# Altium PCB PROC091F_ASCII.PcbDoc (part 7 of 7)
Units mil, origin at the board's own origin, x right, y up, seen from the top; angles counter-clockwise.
Board outline 3590.95 x 906.17 mil, 8 copper layers (Top Layer, GND1, Sig1, PWR1, PWR2, Sig2, GND2, Bottom Layer), stack 63.146 mil thick; 420 components, 316 nets, 1432 pads, 774 vias.
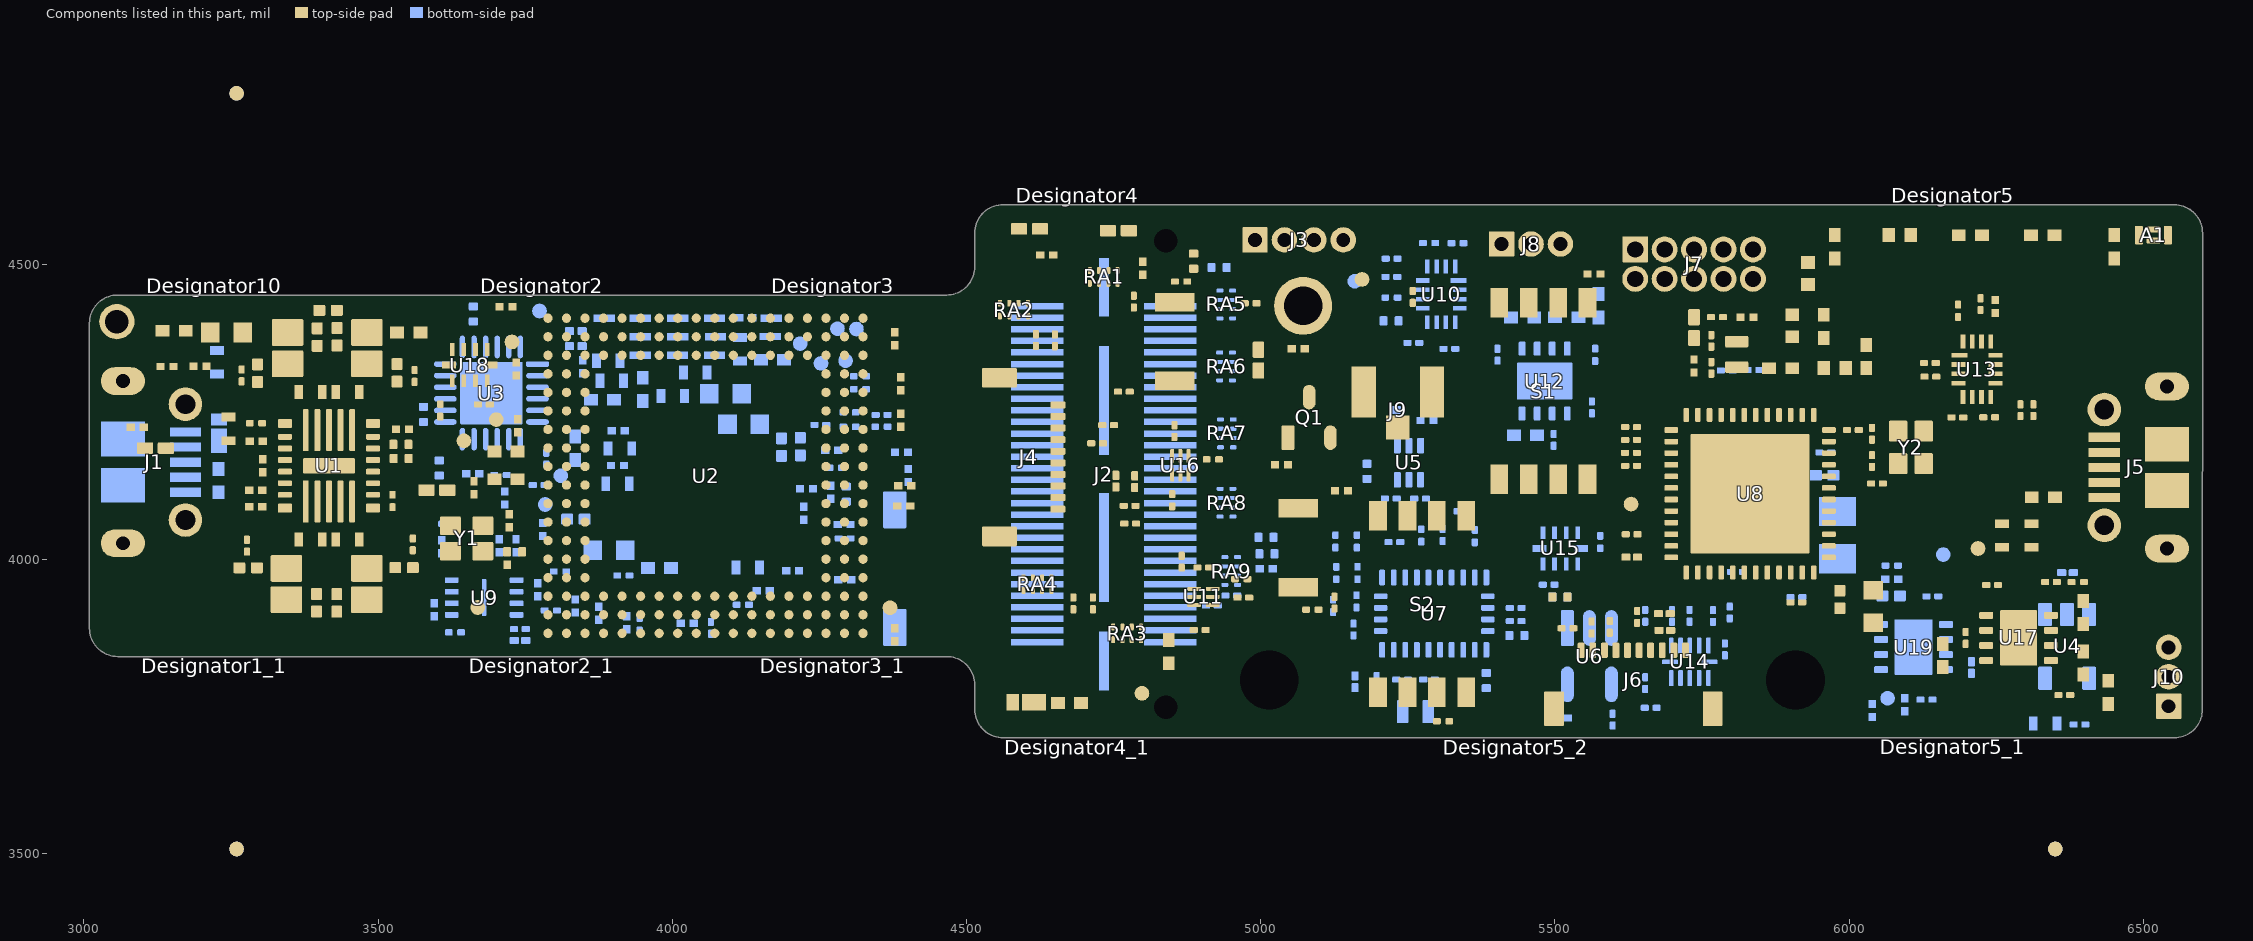
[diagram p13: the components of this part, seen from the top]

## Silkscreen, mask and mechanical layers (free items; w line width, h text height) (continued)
M12 Stackup:
  drawing of 503 lines, arcs and shapes, not listed
  text "Layer" at 8.08,2102.3 h60
  text "Name" at 417.99,2102.3 h60
  text "Material" at 1347.73,2102.3 h60
  text "Thickness" at 2207.5,2102.3 h60
  text "Constant" at 2857.34,2102.3 h60
  text "Board Layer Stack" at 3427.2,2102.3 h60
  text "1" at 8.08,1982.3 h60
  text "Top Overlay" at 417.99,1982.3 h60
  text "2" at 8.08,1862.3 h60
  text "Top Solder" at 417.99,1862.3 h60
  text "Solder Resist" at 1347.73,1862.3 h60
  text "0.50mil" at 2207.5,1862.3 h60
  text "3.5" at 2857.34,1862.3 h60
  text "3" at 8.08,1742.3 h60
  text "Top Layer" at 417.99,1742.3 h60
  text "Copper" at 1347.73,1742.3 h60
  text "1.37mil" at 2207.5,1742.3 h60
  text "4" at 8.08,1622.3 h60
  text "Dielectric1" at 417.99,1622.3 h60
  text "FR-4 High Tg" at 1347.73,1622.3 h60
  text "3.70mil" at 2207.5,1622.3 h60
  text "4.2" at 2857.34,1622.3 h60
  text "5" at 8.08,1502.3 h60
  text "GND1" at 417.99,1502.3 h60
  text "Copper" at 1347.73,1502.3 h60
  text "2.40mil" at 2207.5,1502.3 h60
  text "6" at 8.08,1382.3 h60
  text "Dielectric3" at 417.99,1382.3 h60
  text "FR-4 High Tg" at 1347.73,1382.3 h60
  text "4.50mil" at 2207.5,1382.3 h60
  text "4.2" at 2857.34,1382.3 h60
  text "7" at 8.08,1262.3 h60
  text "Sig1" at 417.99,1262.3 h60
  text "Copper" at 1347.73,1262.3 h60
  text "1.20mil" at 2207.5,1262.3 h60
  text "8" at 8.08,1142.3 h60
  text "Dielectric2" at 417.99,1142.3 h60
  text "FR-4 High Tg" at 1347.73,1142.3 h60
  text "12.00mil" at 2207.5,1142.3 h60
  text "4.2" at 2857.34,1142.3 h60
  text "9" at 8.08,1022.3 h60
  text "PWR1" at 417.99,1022.3 h60
  text "Copper" at 1347.73,1022.3 h60
  text "2.40mil" at 2207.5,1022.3 h60
  text "10" at 8.08,902.3 h60
  text "Dielectric4" at 417.99,902.3 h60
  text "FR-4 High Tg" at 1347.73,902.3 h60
  text "8.00mil" at 2207.5,902.3 h60
  text "4.2" at 2857.34,902.3 h60
  text "11" at 8.08,782.3 h60
  text "PWR2" at 417.99,782.3 h60
  text "Copper" at 1347.73,782.3 h60
  text "2.40mil" at 2207.5,782.3 h60
  text "12" at 8.08,662.3 h60
  text "Dielectric5" at 417.99,662.3 h60
  text "FR-4 High Tg" at 1347.73,662.3 h60
  text "12.00mil" at 2207.5,662.3 h60
  text "4.2" at 2857.34,662.3 h60
  text "13" at 8.08,542.3 h60
  text "Sig2" at 417.99,542.3 h60
  text "Copper" at 1347.73,542.3 h60
  text "1.20mil" at 2207.5,542.3 h60
  text "14" at 8.08,422.3 h60
  text "Dielectric8" at 417.99,422.3 h60
  text "FR-4 High Tg" at 1347.73,422.3 h60
  text "4.50mil" at 2207.5,422.3 h60
  text "4.2" at 2857.34,422.3 h60
  text "15" at 8.08,302.3 h60
  text "GND2" at 417.99,302.3 h60
  text "Copper" at 1347.73,302.3 h60
  text "2.40mil" at 2207.5,302.3 h60
  text "16" at 8.08,182.3 h60
  text "Dielectric9" at 417.99,182.3 h60
  text "FR-4 High Tg" at 1347.73,182.3 h60
  text "3.70mil" at 2207.5,182.3 h60
  text "4.2" at 2857.34,182.3 h60
  text "17" at 8.08,62.3 h60
  text "Bottom Layer" at 417.99,62.3 h60
  text "Copper" at 1347.73,62.3 h60
  text "1.37mil" at 2207.5,62.3 h60
  text "18" at 8.08,-57.7 h60
  text "Bottom Solder" at 417.99,-57.7 h60
  text "Solder Resist" at 1347.73,-57.7 h60
  text "0.50mil" at 2207.5,-57.7 h60
  text "3.5" at 2857.34,-57.7 h60
  text "19" at 8.08,-177.7 h60
  text "Bottom Overlay" at 417.99,-177.7 h60
  text ".Layer_Name" at 577,-858.49 h60
M13 Component Bodies Top:
  text ".Layer_Name" at 577,-858.49 h60
M14 Component Bodies Bottom:
  text ".Layer_Name" at 577,-858.49 h60
M15 Courtyards Top:
  text ".Layer_Name" at 577,-858.49 h60
M16 Courtyards Bottom:
  text ".Layer_Name" at 577,-858.49 h60
Drill Drawing:
  circle w10: c7603.25,4734.77 r16.58
  circle w10: c7603.25,4734.77 r27.63
  circle w10: c7603.25,3367.25 r27.63
  lines w10: 7575.63,3463.95 7603.25,3477.76 7630.88,3463.95 7617.07,3491.57 7630.88,3519.2 7603.25,3505.39 7575.63,3519.2 7589.44,3491.57 7575.63,3463.95 ; 7575.63,3602.08 7589.44,3602.08 7603.25,3588.27 7617.07,3602.08 7630.88,3602.08 7617.07,3615.89 7630.88,3629.71 7617.07,3629.71 7603.25,3643.52 7589.44,3629.71 7575.63,3629.71 7589.44,3615.89 7575.63,3602.08 ; 7575.63,3726.4 7589.44,3726.4 7589.44,3712.59 7617.07,3712.59 7617.07,3726.4 7630.88,3726.4 7630.88,3754.03 7617.07,3754.03 7617.07,3767.84 7589.44,3767.84 7589.44,3754.03 7575.63,3754.03 7575.63,3726.4 ; 7575.63,3836.91 7603.25,3850.72 7630.88,3836.91 7617.07,3864.53 7630.88,3892.16 7603.25,3878.35 7575.63,3892.16 7589.44,3864.53 7575.63,3836.91 ; 7575.63,3988.85 7603.25,3961.23 7630.88,3988.85 7603.25,4016.48 7575.63,3988.85 ; 7575.63,4099.36 7589.44,4099.36 7589.44,4085.55 7617.07,4085.55 7617.07,4099.36 7630.88,4099.36 7630.88,4126.99 7617.07,4126.99 7617.07,4140.8 7589.44,4140.8 7589.44,4126.99 7575.63,4126.99 7575.63,4099.36 ; 7575.63,4265.12 7630.88,4265.12 7603.25,4209.87 7575.63,4265.12 ; 7575.63,4334.19 7575.63,4348 7589.44,4361.81 7575.63,4375.63 7575.63,4389.44 7589.44,4389.44 7603.25,4375.63 7617.07,4389.44 7630.88,4389.44 7630.88,4375.63 7617.07,4361.81 7630.88,4348 7630.88,4334.19 7617.07,4334.19 7603.25,4348 7589.44,4334.19 7575.63,4334.19 ; 7575.63,4458.51 7630.88,4458.51 7630.88,4513.76 7575.63,4513.76 7575.63,4458.51 ; 7575.63,4638.08 7630.88,4638.08 7603.25,4582.83 7575.63,4638.08 ; 7575.63,4831.47 7630.88,4831.47 7630.88,4886.72 7575.63,4886.72 7575.63,4831.47 ; 7586.68,3475 7603.25,3483.28 7619.83,3475 7611.54,3491.57 7619.83,3508.15 7603.25,3499.86 7586.68,3508.15 7594.97,3491.57 7586.68,3475 ; 7586.68,4104.88 7594.97,4104.88 7594.97,4096.6 7611.54,4096.6 7611.54,4104.88 7619.83,4104.88 7619.83,4121.46 7611.54,4121.46 7611.54,4129.75 7594.97,4129.75 7594.97,4121.46 7586.68,4121.46 7586.68,4104.88 ; 7586.68,4627.03 7619.83,4627.03 7603.25,4593.88 7586.68,4627.03 ; 7586.68,4842.52 7619.83,4842.52 7619.83,4875.67 7586.68,4875.67 7586.68,4842.52
  lines w12: 7525.54,3302.33 10757.03,3302.33 ; 7525.54,4918.49 10757.03,4918.49 ; 7863.4,3178.01 7863.4,5042.81 ; 8195.4,3178.01 8195.4,5042.81 ; 8831.96,3178.01 8831.96,5042.81 ; 9091.1,3178.01 9091.1,5042.81 ; 9466.26,3178.01 9466.26,5042.81 ; 10190.59,3178.01 10190.59,5042.81 ; 7525.54,3178.01 10757.03,3178.01 10757.03,5042.81 7525.54,5042.81 7525.54,3178.01
  text "Symbol" at 7600.13,4955.79 h72
  text "Quantity" at 7900.7,4955.79 h72
  text "Finished Hole Size" at 8232.7,4955.79 h72
  text "Plated" at 8869.26,4955.79 h72
  text "Hole Type" at 9128.4,4955.79 h72
  text "Drill Layer Pair" at 9503.56,4955.79 h72
  text "Hole Tolerance" at 10227.89,4955.79 h72
  text "36" at 7900.7,4831.47 h60
  text "7.87mil" at 8232.7,4831.47 h60
  text "PTH" at 8869.26,4831.47 h60
  text "Round" at 9128.4,4831.47 h60
  text "Top Layer - Bottom Layer" at 9503.56,4831.47 h60
  text "626" at 7900.7,4707.15 h60
  text "8.00mil" at 8232.7,4707.15 h60
  text "PTH" at 8869.26,4707.15 h60
  text "Round" at 9128.4,4707.15 h60
  text "Top Layer - Bottom Layer" at 9503.56,4707.15 h60
  text "112" at 7900.7,4582.83 h60
  text "8.00mil" at 8232.7,4582.83 h60
  text "PTH" at 8869.26,4582.83 h60
  text "Round" at 9128.4,4582.83 h60
  text "Top Layer - Bottom Layer" at 9503.56,4582.83 h60
  text "+/-3.00mil" at 10227.89,4582.83 h60
  text "10" at 7900.7,4458.51 h60
  text "23.62mil" at 8232.7,4458.51 h60
  text "PTH" at 8869.26,4458.51 h60
  text "Round" at 9128.4,4458.51 h60
  text "Top Layer - Bottom Layer" at 9503.56,4458.51 h60
  text "4" at 7900.7,4334.19 h60
  text "23.62mil" at 8232.7,4334.19 h60
  text "PTH" at 8869.26,4334.19 h60
  text "Slot" at 9128.4,4334.19 h60
  text "Top Layer - Bottom Layer" at 9503.56,4334.19 h60
  text "10" at 7900.7,4209.87 h60
  text "27.56mil" at 8232.7,4209.87 h60
  text "PTH" at 8869.26,4209.87 h60
  text "Round" at 9128.4,4209.87 h60
  text "Top Layer - Bottom Layer" at 9503.56,4209.87 h60
  text "33" at 7900.7,4085.55 h60
  text "32.00mil" at 8232.7,4085.55 h60
  text "NPTH" at 8869.26,4085.55 h60
  text "Round" at 9128.4,4085.55 h60
  text "Top Layer - Bottom Layer" at 9503.56,4085.55 h60
  text "4" at 7900.7,3961.23 h60
  text "33.47mil" at 8232.7,3961.23 h60
  text "PTH" at 8869.26,3961.23 h60
  text "Round" at 9128.4,3961.23 h60
  text "Top Layer - Bottom Layer" at 9503.56,3961.23 h60
  text "1" at 7900.7,3836.91 h60
  text "40.00mil" at 8232.7,3836.91 h60
  text "PTH" at 8869.26,3836.91 h60
  text "Round" at 9128.4,3836.91 h60
  text "Top Layer - Bottom Layer" at 9503.56,3836.91 h60
  text "2" at 7900.7,3712.59 h60
  text "40.16mil" at 8232.7,3712.59 h60
  text "NPTH" at 8869.26,3712.59 h60
  text "Round" at 9128.4,3712.59 h60
  text "Top Layer - Bottom Layer" at 9503.56,3712.59 h60
  text "1" at 7900.7,3588.27 h60
  text "64.96mil" at 8232.7,3588.27 h60
  text "PTH" at 8869.26,3588.27 h60
  text "Round" at 9128.4,3588.27 h60
  text "Top Layer - Bottom Layer" at 9503.56,3588.27 h60
  text "4" at 7900.7,3463.95 h60
  text "88.00mil" at 8232.7,3463.95 h60
  text "NPTH" at 8869.26,3463.95 h60
  text "Round" at 9128.4,3463.95 h60
  text "Top Layer - Bottom Layer" at 9503.56,3463.95 h60
  text "+/-3.00mil" at 10227.89,3463.95 h60
  text "2" at 7900.7,3339.63 h60
  text "100.00mil" at 8232.7,3339.63 h60
  text "NPTH" at 8869.26,3339.63 h60
  text "Round" at 9128.4,3339.63 h60
  text "Top Layer - Bottom Layer" at 9503.56,3339.63 h60
  text "+/-3.00mil" at 10227.89,3339.63 h60
  text "845 Total" at 7900.7,3215.31 h60
  text "Slot definitions :" at 7600.13,3128.28 h60
  text "Routed Path Length" at 8050.85,3128.28 h60
  text "= Calculated from tool start centre position to tool end centre position." at 8590.58,3128.28 h60
  text "Hole Length" at 8050.85,3078.55 h60
  text "= Routed Path Length + Tool Size = Slot length as defined in the PCB layout" at 8390.78,3078.55 h60
  text ".Layer_Name" at 577,-858.49 h60
M17 Embedded Cavity:
  text ".Layer_Name" at 577,-858.49 h60
M18 Embedded Assembly:
  text ".Layer_Name" at 577,-858.49 h60
M19 Embedded Keepout:
  text ".Layer_Name" at 577,-858.49 h60
Mechanical 21:
  text "Works With TI LaunchPad Logo1" at 56021.02,58034.06 h60
  text "Works With TI LaunchPad Logo1" at 56021.02,58034.06 h60
  text "Logo2" at 54657.52,57702.56 h60
  text "Logo2" at 54657.52,57702.56 h60
  text "LOGO3" at 54889.02,57440.06 h60
  text "LOGO3" at 54889.02,57440.06 h60
  text "FID1" at 55092.65,56736 h60
  text "FID1" at 55092.65,56736 h60
  text "FID2" at 55391.65,56726 h60
  text "FID2" at 55391.65,56726 h60
  text "FID6" at 55107.5,56532.5 h60
  text "FID6" at 55107.5,56532.5 h60
  text "FID5" at 55387.5,56532.5 h60
  text "FID5" at 55387.5,56532.5 h60
  text "FID4" at 55668.5,56532.5 h60
  text "FID4" at 55668.5,56532.5 h60
  text "FID3" at 55948.5,56532.5 h60
  text "FID3" at 55948.5,56532.5 h60
  text "ESD Susceptible1" at 56694.52,56524.06 h60
  text "ESD Susceptible1" at 56694.52,56524.06 h60
  text "CAUTION HOT SURFACE1" at 57228.02,56277.06 h60
  text "CAUTION HOT SURFACE1" at 57228.02,56277.06 h60
  text "For evaluation only; not FCC approved for resale." at 54661.42,56095.48 h60 r90
  text "For evaluation only; not FCC approved for resale." at 54661.42,56095.48 h60 r90
  text "Logo1" at 54419.02,55121.06 h60
  text "Logo1" at 54419.02,55121.06 h60
  text "R73" at 57212.4,54825.61 h60
  text "R73" at 57212.4,54825.61 h60
  text "J17" at 56047,54802 h60
  text "J17" at 56047,54802 h60
  text "J4" at 57338,54802 h60
  text "J4" at 57338,54802 h60
  text "J3" at 58017,54787 h60
  text "J3" at 58017,54787 h60
  text "R14" at 57970,54727 h60
  text "R14" at 57970,54727 h60
  text "Q2" at 58016.76,54608.4 h60
  text "Q2" at 58016.76,54608.4 h60
  text "R128" at 57968,54595 h60
  text "R128" at 57968,54595 h60
  text "DS2" at 58182.15,54571 h60
  text "DS2" at 58182.15,54571 h60
  text "R118" at 58197,54456 h60
  text "R118" at 58197,54456 h60
  text "D4" at 58067.44,54360.39 h60
  text "D4" at 58067.44,54360.39 h60
  text "R351" at 57689,54352 h60
  text "R351" at 57689,54352 h60
  text "R350" at 57689,54300 h60
  text "R350" at 57689,54300 h60
  text "R220" at 57803,54206 h60
  text "R220" at 57803,54206 h60
  text "R223" at 57737.75,53914.35 h60
  text "R223" at 57737.75,53914.35 h60
  text "R227" at 57977.49,53913.76 h60
  text "R227" at 57977.49,53913.76 h60
  text "R190" at 56624.85,53824.59 h60
  text "R190" at 56624.85,53824.59 h60
  text "R189" at 56679.85,53824.59 h60
  text "R189" at 56679.85,53824.59 h60
  text "J15" at 57338.02,53806.06 h60
  text "J15" at 57338.02,53806.06 h60
  text "C66" at 56801.85,53741.59 h60
  text "C66" at 56801.85,53741.59 h60
  text "R67" at 57504.63,53724 h60
  text "R67" at 57504.63,53724 h60
  text "C67" at 56534.85,53719.59 h60
  text "R196" at 56534.85,53719.59 h60
  text "C67" at 56534.85,53719.59 h60
  text "R196" at 56534.85,53719.59 h60
  text "R192" at 56584.85,53719.59 h60
  text "R192" at 56584.85,53719.59 h60
  text "R195" at 56634.85,53719.59 h60
  text "R195" at 56634.85,53719.59 h60
  text "R194" at 56684.85,53719.59 h60
  text "R194" at 56684.85,53719.59 h60
  text "R184" at 56801.85,53719.59 h60
  text "R184" at 56801.85,53719.59 h60
  text "R183" at 56854.85,53719.59 h60
  text "R183" at 56854.85,53719.59 h60
  text "R182" at 56904.85,53719.59 h60
  text "R182" at 56904.85,53719.59 h60
  text "R198" at 56397,53660 h60
  text "R198" at 56397,53660 h60
  text "R70" at 57504.63,53624 h60
  text "R70" at 57504.63,53624 h60
  text "U15" at 56578.85,53601.59 h60
  text "U15" at 56578.85,53601.59 h60
  text "R204" at 57113.07,53589.4 h60
  text "R204" at 57113.07,53589.4 h60
  text "R162" at 56492,53581 h60
  text "R162" at 56492,53581 h60
  text "R60" at 57501,53579 h60
  text "R60" at 57501,53579 h60
  text "R161" at 56492,53544 h60
  text "R161" at 56492,53544 h60
  text "R72" at 57727.07,53524 h60
  text "R72" at 57727.07,53524 h60
  text "R199" at 56330,53492.43 h60
  text "R199" at 56330,53492.43 h60
  text "J10" at 55887,53488 h60
  text "J10" at 55887,53488 h60
  text "R64" at 57718,53480 h60
  text "R64" at 57718,53480 h60
  text "R152" at 57977.49,53479.76 h60
  text "R152" at 57977.49,53479.76 h60
  text "C53" at 57216.92,53466.99 h60
  text "C53" at 57216.92,53466.99 h60
  text "L6" at 57283.85,53449.59 h60
  text "L6" at 57283.85,53449.59 h60
  text "C56" at 57111.85,53444.59 h60
  text "C56" at 57111.85,53444.59 h60
  text "C54" at 57163.92,53444.99 h60
  text "C54" at 57163.92,53444.99 h60
  text "R218" at 56330,53437.43 h60
  text "R218" at 56330,53437.43 h60
  text "R76" at 57727.07,53424 h60
  text "R76" at 57727.07,53424 h60
  text "R200" at 56316.85,53386.59 h60
  text "R200" at 56316.85,53386.59 h60
  text "U7" at 57968.92,53371.46 h60
  text "U7" at 57968.92,53371.46 h60
  text "R81" at 57504.02,53324 h60
  text "R81" at 57504.02,53324 h60
  text "R78" at 57727,53324 h60
  text "R78" at 57727,53324 h60
  text "C36" at 56457.8,53322.99 h60
  text "C36" at 56457.8,53322.99 h60
  text "R201" at 57132.85,53319.59 h60
  text "R201" at 57132.85,53319.59 h60
  text "R206" at 56316.85,53286.59 h60
  text "R206" at 56316.85,53286.59 h60
  text "C52" at 57132.85,53269.59 h60
  text "C52" at 57132.85,53269.59 h60
  text "R207" at 56316.85,53236.59 h60
  text "R207" at 56316.85,53236.59 h60
  text "R85" at 57725,53225 h60
  text "R85" at 57725,53225 h60
  text "C51" at 57131.85,53216.59 h60
  text "C51" at 57131.85,53216.59 h60
  text "R208" at 56316.85,53186.59 h60
  text "R208" at 56316.85,53186.59 h60
  text "R394" at 57716,53187 h60
  text "R394" at 57716,53187 h60
  text "R393" at 57755,53185 h60
  text "R393" at 57755,53185 h60
  text "R61" at 57501,53174 h60
  text "R61" at 57501,53174 h60
  text "L5" at 57153.52,53152.08 h60
  text "L5" at 57153.52,53152.08 h60
  text "C59" at 56452,53137 h60
  text "C59" at 56452,53137 h60
  text "R89" at 57732,53111 h60
  text "R89" at 57732,53111 h60
  text "C58" at 56436.57,53084.4 h60
  text "C58" at 56436.57,53084.4 h60
  text "Y2" at 57122.77,53068.99 h60
  text "Y2" at 57122.77,53068.99 h60
  text "C57" at 56972.85,53059.59 h60
  text "C57" at 56972.85,53059.59 h60
  text "C70" at 56589.23,53056.59 h60
  text "C70" at 56589.23,53056.59 h60
  text "C68" at 56737.85,53056.59 h60
  text "C68" at 56737.85,53056.59 h60
  text "J19" at 58033,53057 h60
  text "J19" at 58033,53057 h60
  text "C69" at 56479.07,53037.4 h60
  text "C69" at 56479.07,53037.4 h60
  text "R90" at 57504.63,53024 h60
  text "R90" at 57504.63,53024 h60
  text "R91" at 57727.07,53024 h60
  text "R91" at 57727.07,53024 h60
  text "R150" at 56532,53006 h60
  text "R150" at 56532,53006 h60
  text "C42" at 56567.65,53006 h60
  text "C42" at 56567.65,53006 h60
  text "C30" at 56412.02,52997.6 h60
  text "C30" at 56412.02,52997.6 h60
  text "R95" at 57721,52978 h60
  text "R95" at 57721,52978 h60
  text "R210" at 56479.85,52975.59 h60
  text "R210" at 56479.85,52975.59 h60
  text "R211" at 56550.85,52975.59 h60
  text "R211" at 56550.85,52975.59 h60
  text "R212" at 56580.85,52975.59 h60
  text "R212" at 56580.85,52975.59 h60
  text "R213" at 56631.85,52975.59 h60
  text "R213" at 56631.85,52975.59 h60
  text "R214" at 56682.85,52975.59 h60
  text "R214" at 56682.85,52975.59 h60
  text "R215" at 56733.85,52975.59 h60
  text "R215" at 56733.85,52975.59 h60
  text "R216" at 56784.85,52975.59 h60
  text "R216" at 56784.85,52975.59 h60
  text "R217" at 56833.85,52975.59 h60
  text "R217" at 56833.85,52975.59 h60
  text "U6" at 56399.87,52935.6 h60
  text "U6" at 56399.87,52935.6 h60
  text "R93" at 57504.63,52924 h60
  text "R93" at 57504.63,52924 h60
  text "R92" at 57727.07,52924 h60
  text "R92" at 57727.07,52924 h60
  text "C29" at 56337.49,52919.55 h60
  text "C29" at 56337.49,52919.55 h60
  text "C28" at 56582,52907 h60
  text "C28" at 56582,52907 h60
  text "R187" at 57077,52877 h60
  text "R187" at 57077,52877 h60
  text "R193" at 57181.62,52877 h60
  text "R193" at 57181.62,52877 h60
  text "C55" at 57312,52877 h60
  text "C55" at 57312,52877 h60
  text "U17" at 56762,52840 h60
  text "U17" at 56762,52840 h60
  text "R185" at 57076.48,52827.58 h60
  text "R185" at 57076.48,52827.58 h60
  text "R186" at 57182,52827 h60
  text "R186" at 57182,52827 h60
  text "R181" at 57312,52827 h60
  text "R181" at 57312,52827 h60
  text "R94" at 57504.63,52824 h60
  text "R94" at 57504.63,52824 h60
  text "C62" at 56584.37,52807.06 h60
  text "C62" at 56584.37,52807.06 h60
  text "R304" at 57236,52750 h60
  text "R304" at 57236,52750 h60
  text "R221" at 56507.09,52747.53 h60
  text "R221" at 56507.09,52747.53 h60
  text "U20" at 57186,52741 h60
  text "U20" at 57186,52741 h60
  text "C65" at 56602,52736.38 h60
  text "C65" at 56602,52736.38 h60
  text "C7" at 57154.28,52735.36 h60
  text "C7" at 57154.28,52735.36 h60
  text "J13" at 56412,52725 h60
  text "J13" at 56412,52725 h60
  text "R306" at 57237,52708 h60
  text "R306" at 57237,52708 h60
  text "SW1" at 57858.65,52699 h60
  text "SW1" at 57858.65,52699 h60
  text "U25" at 56979,52678 h60
  text "U25" at 56979,52678 h60
  text "R310" at 57415,52671 h60
  text "R310" at 57415,52671 h60
  text "R151" at 56897,52642 h60
  text "R151" at 56897,52642 h60
  text "R311" at 57415,52636 h60
  text "R311" at 57415,52636 h60
  text "S7" at 56399,52624 h60
  text "S7" at 56399,52624 h60
  text "R301" at 57372,52599 h60
  text "R301" at 57372,52599 h60
  text "C73" at 56262.62,52569.53 h60
  text "C73" at 56262.62,52569.53 h60
  text "R338" at 56787.37,52555.06 h60
  text "R338" at 56787.37,52555.06 h60
  text "U26" at 56919.12,52539.06 h60
  text "U26" at 56919.12,52539.06 h60
  text "R209" at 56801,52497 h60
  text "R209" at 56801,52497 h60
  text "S10" at 56399,52494 h60
  text "S10" at 56399,52494 h60
  text "C27" at 56283.06,52418 h60
  text "C27" at 56283.06,52418 h60
  text "C50" at 55666,52407 h60
  text "C50" at 55666,52407 h60
  text "S5" at 56399,52381 h60
  text "S5" at 56399,52381 h60
  text "U28" at 56817,52365 h60
  text "U28" at 56817,52365 h60
  text "J14" at 57878.02,52346.06 h60
  text "J14" at 57878.02,52346.06 h60
  text "R24" at 56760,52338 h60
  text "R24" at 56760,52338 h60
  text "U11" at 57728.34,52328.92 h60
  text "U11" at 57728.34,52328.92 h60
  text "R339" at 56204.5,52306.5 h60
  text "R339" at 56204.5,52306.5 h60
  text "S6" at 56399,52288 h60
  text "S6" at 56399,52288 h60
  text "R25" at 56350,52285 h60
  text "R25" at 56350,52285 h60
  text "R16" at 56048,52270.5 h60
  text "R16" at 56048,52270.5 h60
  text "C72" at 55979,52269.62 h60
  text "C72" at 55979,52269.62 h60
  text "R173" at 57089,52231 h60
  text "R173" at 57089,52231 h60
  text "C94" at 56205,52229 h60
  text "C94" at 56205,52229 h60
  text "R18" at 56764,52229 h60
  text "R18" at 56764,52229 h60
  text "U33" at 56923.22,52200.19 h60
  text "U33" at 56923.22,52200.19 h60
  text "U19" at 57072,52191 h60
  text "U19" at 57072,52191 h60
  text "R175" at 57160.32,52177.62 h60
  text "R175" at 57160.32,52177.62 h60
  text "S11" at 56399,52175 h60
  text "S11" at 56399,52175 h60
  text "R41" at 56339.02,52156.06 h60
  text "R41" at 56339.02,52156.06 h60
  text "SW2" at 58116.65,52147 h60
  text "SW2" at 58116.65,52147 h60
  text "R19" at 56771,52133 h60
  text "R19" at 56771,52133 h60
  text "C112" at 56048,52118 h60
  text "C112" at 56048,52118 h60
  text "C117" at 56270.24,52116 h60
  text "C117" at 56270.24,52116 h60
  text "C49" at 57105,52095 h60
  text "C49" at 57105,52095 h60
  text "R180" at 57145,52095 h60
  text "R180" at 57145,52095 h60
  text "R172" at 57063,52089 h60
  text "R172" at 57063,52089 h60
  text "LBL1" at 58550.37,52085.06 h60
  text "LBL1" at 58550.37,52085.06 h60
  text "J9" at 55627.11,52069.11 h60
  text "J9" at 55627.11,52069.11 h60
  text "S3" at 56339,52044 h60
  text "S3" at 56339,52044 h60
  text "R8" at 56993,52019 h60
  text "R8" at 56993,52019 h60
  text "U1" at 56726,52004 h60
  text "U1" at 56726,52004 h60
  text "R229" at 56004.36,51991.59 h60
  text "R229" at 56004.36,51991.59 h60
  text "C2" at 56692,51990.69 h60
  text "C2" at 56692,51990.69 h60
  text "C4" at 57710.2,51977.88 h60
  text "C4" at 57710.2,51977.88 h60
  text "U32" at 56133,51977 h60
  text "U32" at 56133,51977 h60
  text "R1" at 57048,51952 h60
  text "R1" at 57048,51952 h60
  text "R117" at 57862.62,51943.53 h60
  text "R117" at 57862.62,51943.53 h60
  text "R144" at 56003.74,51942.05 h60
  text "R144" at 56003.74,51942.05 h60
  text "R3" at 56919,51937 h60
  text "R3" at 56919,51937 h60
  text "Q1" at 57946.65,51928 h60
  text "Q1" at 57946.65,51928 h60
  text "R261" at 57830.74,51910.17 h60
  text "R261" at 57830.74,51910.17 h60
  text "R54" at 56005,51891 h60
  text "R54" at 56005,51891 h60
  text "DS1" at 58120,51890 h60
  text "DS1" at 58120,51890 h60
  text "C76" at 56572.13,51859.91 h60
  text "C76" at 56572.13,51859.91 h60
  text "S1" at 57770.72,51851 h60
  text "S1" at 57770.72,51851 h60
  text "L7" at 56445.37,51847.06 h60
  text "L7" at 56445.37,51847.06 h60
  text "R270" at 56005,51841 h60
  text "R270" at 56005,51841 h60
  text "R6" at 57000,51841 h60
  text "R6" at 57000,51841 h60
  text "J28" at 56344.97,51821.39 h60
  text "J28" at 56344.97,51821.39 h60
  text "R260" at 57790,51821 h60
  text "R260" at 57790,51821 h60
  text "C111" at 56141.07,51805 h60
  text "C111" at 56141.07,51805 h60
  text "U3" at 56906,51797 h60
  text "U3" at 56906,51797 h60
  text "U12" at 56512.86,51794.81 h60
  text "U12" at 56512.86,51794.81 h60
  text "R269" at 56005,51791 h60
  text "R269" at 56005,51791 h60
  text "R113" at 56205.45,51785.73 h60
  text "R113" at 56205.45,51785.73 h60
  text "J1" at 57964,51782 h60
  text "J1" at 57964,51782 h60
  text "R268" at 56005,51736 h60
  text "R268" at 56005,51736 h60
  text "H2" at 59278.02,51732.06 h60
  text "H2" at 59278.02,51732.06 h60
  text "R256" at 56477.37,51691.06 h60
  text "R256" at 56477.37,51691.06 h60
  text "R30" at 56005,51686 h60
  text "R30" at 56005,51686 h60
  text "R321" at 57316,51648 h60
  text "R321" at 57316,51648 h60
  text "R29" at 56005,51636 h60
  text "R29" at 56005,51636 h60
  text "R324" at 57296,51608 h60
  text "R324" at 57296,51608 h60
  text "Logo4" at 58802.02,51607.06 h60
  text "Logo4" at 58802.02,51607.06 h60
  text "U23" at 57286.85,51605.4 h60
  text "U23" at 57286.85,51605.4 h60
  text "C3" at 57912.37,51605.06 h60
  text "C3" at 57912.37,51605.06 h60
  text "C26" at 57052.91,51598.66 h60
  text "C26" at 57052.91,51598.66 h60
  text "H1" at 58428.02,51592.06 h60
  text "H1" at 58428.02,51592.06 h60
  text "R28" at 56005,51581 h60
  text "R28" at 56005,51581 h60
  text "R313" at 56661.74,51578.44 h60
  text "R313" at 56661.74,51578.44 h60
  text "R331" at 57329.82,51571.99 h60
  text "R331" at 57329.82,51571.99 h60
  text "D11" at 56775.76,51570.07 h60
  text "D11" at 56775.76,51570.07 h60
  text "R291" at 56531,51569 h60
  text "R291" at 56531,51569 h60
  text "C81" at 57580,51554 h60
  text "C81" at 57580,51554 h60
  text "R317" at 57316.07,51536.47 h60
  text "R317" at 57316.07,51536.47 h60
  text "R27" at 56005,51531 h60
  text "R27" at 56005,51531 h60
  text "L9" at 56729,51530 h60
  text "L9" at 56729,51530 h60
  text "P1" at 56364.86,51510 h60
  text "P1" at 56364.86,51510 h60
  text "R396" at 56236,51508 h60
  text "R396" at 56236,51508 h60
  text "R332" at 57303,51501 h60
  text "R332" at 57303,51501 h60
  text "R397" at 56156,51488 h60
  text "R397" at 56156,51488 h60
  text "R21" at 56005,51481 h60
  text "R21" at 56005,51481 h60
  text "C120" at 56233,51472 h60
  text "C120" at 56233,51472 h60
  text "U30" at 56169,51440 h60
  text "U30" at 56169,51440 h60
  text "R20" at 56005,51431 h60
  text "R20" at 56005,51431 h60
  text "R271" at 57433.29,51414.06 h60
  text "R271" at 57433.29,51414.06 h60
  text "C82" at 57571,51411 h60
  text "C82" at 57571,51411 h60
  text "R395" at 56133.32,51388.04 h60
  text "R395" at 56133.32,51388.04 h60
  text "R246" at 56005,51381 h60
  text "R246" at 56005,51381 h60
  text "C78" at 57741,51368 h60
  text "C78" at 57741,51368 h60
  text "J2" at 57964,51337 h60
  text "J2" at 57964,51337 h60
  text "R243" at 56005,51331 h60
  text "R243" at 56005,51331 h60
  text "L8" at 57711,51315 h60
  text "L8" at 57711,51315 h60
  text "R309" at 56935.21,51298.07 h60
  text "R309" at 56935.21,51298.07 h60
  text "U13" at 57467,51295 h60
  text "U13" at 57467,51295 h60
  text "C88" at 56223,51294 h60
  text "C88" at 56223,51294 h60
  text "C108" at 56561,51275 h60
  text "C108" at 56561,51275 h60
  text "U29" at 56752,51266 h60
  text "U29" at 56752,51266 h60
  text "J27" at 56378.3,51228.62 h60
  text "J27" at 56378.3,51228.62 h60
  text "R115" at 56222.08,51202.58 h60
  text "R115" at 56222.08,51202.58 h60
  text "C99" at 57036,51199 h60
  text "C99" at 57036,51199 h60
  text "H3" at 59278.02,51192.06 h60
  text "H3" at 59278.02,51192.06 h60
  text "C100" at 56947,51182 h60
  text "C100" at 56947,51182 h60
  text "H4" at 59658.02,51182.06 h60
  text "H4" at 59658.02,51182.06 h60
  text "H5" at 60008.02,51182.06 h60
  text "H5" at 60008.02,51182.06 h60
  text "U31" at 56061,51181 h60
  text "U31" at 56061,51181 h60
  text "C102" at 56496,51175 h60
  text "C102" at 56496,51175 h60
  text "H6" at 60368.02,51172.06 h60
  text "H6" at 60368.02,51172.06 h60
  text "C103" at 56629,51171 h60
  text "C103" at 56629,51171 h60
  text "C87" at 57290,51136 h60
  text "C87" at 57290,51136 h60
  text "R318" at 58884.02,51117.68 h60
  text "R318" at 58884.02,51117.68 h60
  text "R315" at 58534.02,51114.06 h60
  text "R315" at 58534.02,51114.06 h60
  text "C91" at 57811,51090 h60
  text "C91" at 57811,51090 h60
  text "R131" at 55699.43,51041.54 h60
  text "R131" at 55699.43,51041.54 h60
  text "C97" at 56692.79,51024.94 h60
  text "C97" at 56692.79,51024.94 h60
  text "C109" at 56067,50998 h60
  text "C109" at 56067,50998 h60
  text "R140" at 55967.43,50996.54 h60
  text "R140" at 55967.43,50996.54 h60
  text "R133" at 55707.43,50987.54 h60
  text "R133" at 55707.43,50987.54 h60
  text "R139" at 55829.43,50987.54 h60
  text "R139" at 55829.43,50987.54 h60
  text "C79" at 57637.52,50972.56 h60
  text "C79" at 57637.52,50972.56 h60
  text "R135" at 55624.43,50940.54 h60
  text "R135" at 55624.43,50940.54 h60
  text "R136" at 55745.43,50940.54 h60
  text "R136" at 55745.43,50940.54 h60
  text "R141" at 55876.43,50932.54 h60
  text "R141" at 55876.43,50932.54 h60
  text "R134" at 55707.43,50906.54 h60
  text "R134" at 55707.43,50906.54 h60
  text "R138" at 55829.43,50906.54 h60
  text "R138" at 55829.43,50906.54 h60
  text "R132" at 55625.43,50905.54 h60
  text "R132" at 55625.43,50905.54 h60
  text "R137" at 55745.43,50905.54 h60
  text "R137" at 55745.43,50905.54 h60
  text "R143" at 55876.43,50897.54 h60
  text "R143" at 55876.43,50897.54 h60
  text "R116" at 57765.62,50891.53 h60
  text "R116" at 57765.62,50891.53 h60
  text "P7" at 57484.37,50880.06 h60
  text "P7" at 57484.37,50880.06 h60
  text "P3" at 57606.37,50880.06 h60
  text "P3" at 57606.37,50880.06 h60
  text "TP1" at 57933.94,50875.28 h60
  text "TP1" at 57933.94,50875.28 h60
  text "D14" at 58099.72,50838 h60
  text "D14" at 58099.72,50838 h60
  text "P4" at 55566,50798.61 h60
  text "P4" at 55566,50798.61 h60
  text "J18" at 55787.63,50773.94 h60
  text "J18" at 55787.63,50773.94 h60
  text "J20" at 56602.63,50773.94 h60
  text "J20" at 56602.63,50773.94 h60
  text "P2" at 57944,50712.02 h60
  text "P2" at 57944,50712.02 h60
  text "C23" at 57473,50628 h60
  text "C23" at 57473,50628 h60
  text "F1" at 57792,50601 h60
  text "F1" at 57792,50601 h60
  text "P5" at 55566,50598.75 h60
  text "P5" at 55566,50598.75 h60
  text "J16" at 55938,50552 h60
  text "J16" at 55938,50552 h60
  text "R142" at 56107.74,50443.95 h60 r90
  text "R142" at 56107.74,50443.95 h60 r90
  text "P6" at 55566,50401 h60
  text "P6" at 55566,50401 h60
  text "D1" at 57757.37,50398.06 h60
  text "D1" at 57757.37,50398.06 h60
  text "D8" at 56409.81,50257.81 h60
  text "D8" at 56409.81,50257.81 h60
  text "DS4" at 55968,50257 h60
  text "DS4" at 55968,50257 h60
  text "DS3" at 56037,50256 h60
  text "DS3" at 56037,50256 h60
  text "D6" at 56255,50256 h60
  text "D6" at 56255,50256 h60
  text "D10" at 55995,50254.54 h60
  text "D10" at 55995,50254.54 h60
  text "D9" at 56115,50254.54 h60
  text "D9" at 56115,50254.54 h60
  text "D5" at 56185,50254.54 h60
  text "D5" at 56185,50254.54 h60
  text "D7" at 56329.19,50254.54 h60
  text "D7" at 56329.19,50254.54 h60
